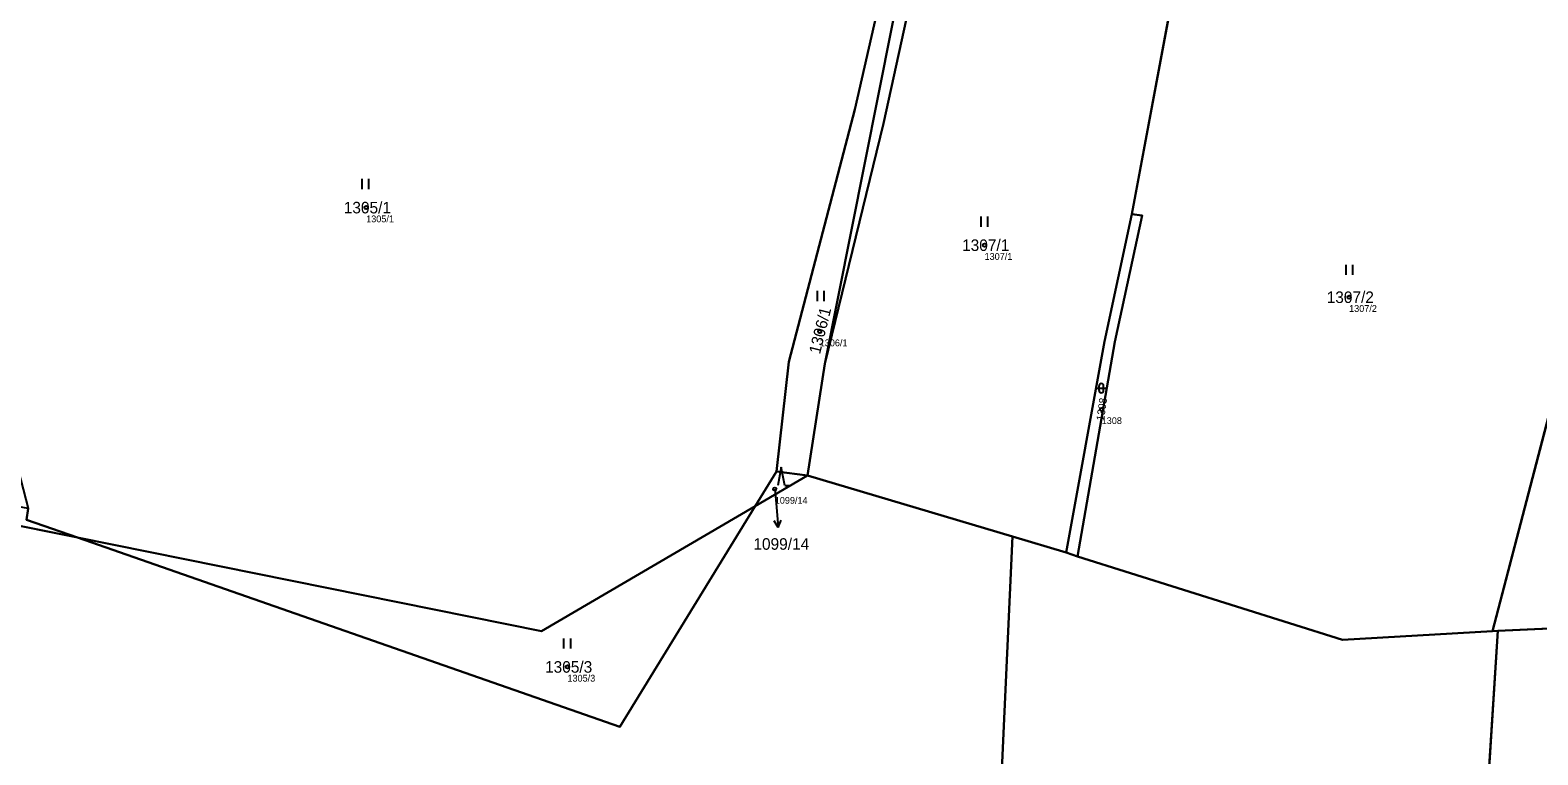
# Model space of a CAD drawing. Extents: x -754731 to -751381, y -1060564 to -1058101.
# Drawn here: x -753239.2 to -753017.1, y -1059498.8 to -1059392.2 of the extents above; entities that cross this region are included whole.
import ezdxf

# ---------------------------------------------------------------- set-up
doc = ezdxf.new("R2010")
doc.units = 0
for name, color, linetype in [('Definiční body', 7, 'Continuous'), ('Hranice parcel', 7, 'Continuous'), ('Parcelní čísla', 7, 'Continuous'), ('Polygon parcely', 7, 'Continuous'), ('Pop  PČ popisy', 7, 'Continuous'), ('Značky kultur', 7, 'Continuous')]:
    doc.layers.add(name, color=color, linetype=linetype)

msp = doc.modelspace()

# ---------------------------------------------------------------- linework, layer by layer
at = {"layer": 'Definiční body'}
for centre in [(-753189.67, -1059418.28), (-753098.61, -1059423.81), (-753044.93, -1059431.47), (-753122.88, -1059436.53), (-753081.36, -1059447.98), (-753129.5, -1059459.71), (-753160.03, -1059485.89)]:
    msp.add_circle(centre, 0.25, dxfattribs=at)
at = {"layer": 'Hranice parcel'}
for p, q in [((-753122.14, -1059441.27), (-753108.33, -1059371.96)), ((-753076.91, -1059419.23), (-753069.61, -1059380.18)), ((-753001.15, -1059393.75), (-753023.79, -1059480.61)), ((-753124.7, -1059457.73), (-753122.14, -1059441.27)), ((-753132.37, -1059462.22), (-753129.23, -1059457.1)), ((-753132.37, -1059462.22), (-753124.7, -1059457.73)), ((-753124.7, -1059457.73), (-753129.23, -1059457.1)), ((-753094.51, -1059466.71), (-753124.7, -1059457.73)), ((-753251.49, -1059462.95), (-753232.16, -1059466.85)), ((-753094.51, -1059466.71), (-753097.3, -1059527.86)), ((-753086.61, -1059469.06), (-753094.51, -1059466.71)), ((-753086.61, -1059469.06), (-753084.91, -1059469.63)), ((-753023.01, -1059480.58), (-752952.57, -1059477.41)), ((-753023.01, -1059480.58), (-753032.16, -1059623.34)), ((-753023.79, -1059480.61), (-753023.01, -1059480.58))]:
    msp.add_line(p, q, dxfattribs=at)
for points in [[(-753129.23, -1059457.1), (-753127.44, -1059440.99), (-753117.69, -1059403.86), (-753110.37, -1059371.53)], [(-753122.14, -1059441.27), (-753113.51, -1059405.91), (-753106.36, -1059373.37), (-753105.74, -1059372.51)], [(-753076.91, -1059419.23), (-753080.95, -1059437.97), (-753086.61, -1059469.06)], [(-753084.91, -1059469.63), (-753079.44, -1059438.04), (-753075.41, -1059419.43), (-753076.91, -1059419.23)], [(-753232.16, -1059466.85), (-753163.85, -1059480.64), (-753132.37, -1059462.22)], [(-753132.37, -1059462.22), (-753152.3, -1059494.72), (-753232.16, -1059466.85)], [(-753239.44, -1059462.59), (-753239.7, -1059464.22), (-753232.16, -1059466.85)], [(-753023.79, -1059480.61), (-753045.91, -1059481.9), (-753084.91, -1059469.63)]]:
    msp.add_lwpolyline(points, dxfattribs=at)
at = {"layer": 'Polygon parcely'}
for points in [[(-753239.44, -1059462.59), (-753239.7, -1059464.22), (-753232.16, -1059466.85), (-753163.85, -1059480.64), (-753132.37, -1059462.22), (-753129.23, -1059457.1), (-753127.44, -1059440.99), (-753117.69, -1059403.86), (-753110.37, -1059371.53), (-753147.19, -1059363.71), (-753183.61, -1059356.78), (-753206.83, -1059350.65), (-753219.49, -1059351.78), (-753239.61, -1059348.46), (-753248.89, -1059342.51), (-753251.38, -1059347.17), (-753248.12, -1059396.35), (-753248.71, -1059432.04), (-753249.99, -1059436.96), (-753251.9, -1059439.87), (-753245.37, -1059439.81)], [(-753122.14, -1059441.27), (-753108.33, -1059371.96), (-753110.37, -1059371.53), (-753117.69, -1059403.86), (-753127.44, -1059440.99), (-753129.23, -1059457.1), (-753124.7, -1059457.73)], [(-753069.61, -1059380.18), (-753105.74, -1059372.51), (-753106.36, -1059373.37), (-753113.51, -1059405.91), (-753122.14, -1059441.27), (-753124.7, -1059457.73), (-753094.51, -1059466.71), (-753086.61, -1059469.06), (-753080.95, -1059437.97), (-753076.91, -1059419.23)], [(-753113.51, -1059405.91), (-753106.36, -1059373.37), (-753105.74, -1059372.51), (-753108.33, -1059371.96), (-753122.14, -1059441.27)], [(-753084.91, -1059469.63), (-753045.91, -1059481.9), (-753023.79, -1059480.61), (-753001.15, -1059393.75), (-753022.88, -1059387.98), (-753046.17, -1059383.23), (-753063.28, -1059382.9), (-753069.61, -1059380.18), (-753076.91, -1059419.23), (-753075.41, -1059419.43), (-753079.44, -1059438.04)], [(-752984.23, -1059398.75), (-753001.15, -1059393.75), (-753023.79, -1059480.61), (-753023.01, -1059480.58), (-752952.57, -1059477.41), (-752940.93, -1059476.89), (-752937.74, -1059463.82), (-752937.1, -1059461.21), (-752923.95, -1059415.07), (-752923.3, -1059412.8)], [(-753079.44, -1059438.04), (-753075.41, -1059419.43), (-753076.91, -1059419.23), (-753080.95, -1059437.97), (-753086.61, -1059469.06), (-753084.91, -1059469.63)], [(-753182.66, -1059567.3), (-753100.43, -1059521.77), (-753097.3, -1059527.86), (-753094.51, -1059466.71), (-753124.7, -1059457.73), (-753132.37, -1059462.22), (-753152.3, -1059494.72), (-753232.16, -1059466.85), (-753251.49, -1059462.95), (-753247.8, -1059512.2)], [(-753124.7, -1059457.73), (-753129.23, -1059457.1), (-753132.37, -1059462.22)], [(-753232.16, -1059466.85), (-753239.7, -1059464.22), (-753239.44, -1059462.59), (-753251.69, -1059460.25), (-753251.49, -1059462.95)], [(-753232.16, -1059466.85), (-753152.3, -1059494.72), (-753132.37, -1059462.22), (-753163.85, -1059480.64)], [(-753045.91, -1059481.9), (-753084.91, -1059469.63), (-753086.61, -1059469.06), (-753094.51, -1059466.71), (-753097.3, -1059527.86), (-753089.43, -1059543.15), (-753094.66, -1059553.62), (-753092.71, -1059600.13), (-753100.71, -1059602.81), (-753102.26, -1059636.83), (-753070.37, -1059630.8), (-753032.16, -1059623.34), (-753023.01, -1059480.58), (-753023.79, -1059480.61)], [(-753008.94, -1059621.27), (-752952.13, -1059591.52), (-752952.57, -1059477.41), (-753023.01, -1059480.58), (-753032.16, -1059623.34)]]:
    msp.add_lwpolyline(points, close=True, dxfattribs=at)
at = {"layer": 'Pop  PČ popisy'}
for p, q in [((-753129.5, -1059459.71), (-753129.24, -1059462.36)), ((-753128.98, -1059465.35), (-753129.57, -1059464.4)), ((-753129.24, -1059462.36), (-753128.98, -1059465.35)), ((-753128.98, -1059465.35), (-753128.57, -1059464.31))]:
    msp.add_line(p, q, dxfattribs=at)
at = {"layer": 'Značky kultur'}
for p, q in [((-753190.26, -1059415.56), (-753190.26, -1059414.06)), ((-753189.26, -1059415.56), (-753189.26, -1059414.06)), ((-753099.12, -1059421.11), (-753099.12, -1059419.61)), ((-753098.12, -1059421.11), (-753098.12, -1059419.61)), ((-753045.37, -1059428.18), (-753045.37, -1059426.68)), ((-753044.37, -1059428.18), (-753044.37, -1059426.68)), ((-753123.21, -1059432.03), (-753123.21, -1059430.53)), ((-753122.21, -1059432.03), (-753122.21, -1059430.53)), ((-753082.09, -1059444.85), (-753080.75, -1059444.85)), ((-753081.76, -1059444.52), (-753081.76, -1059445.19)), ((-753081.08, -1059445.19), (-753081.08, -1059444.52)), ((-753128.54, -1059456.49), (-753129.04, -1059459.17)), ((-753128.04, -1059459.17), (-753128.54, -1059456.49)), ((-753128.04, -1059459.17), (-753127.37, -1059459.17)), ((-753160.54, -1059483.19), (-753160.54, -1059481.69)), ((-753159.54, -1059483.19), (-753159.54, -1059481.69))]:
    msp.add_line(p, q, dxfattribs=at)
for centre, start, end in [((-753081.42, -1059444.52), 0, 180), ((-753081.42, -1059445.19), 180, 359.9879)]:
    msp.add_arc(centre, 0.335, start, end, dxfattribs=at)

# ---------------------------------------------------------------- texts
at = {"layer": 'Definiční body'}
for s, p in [('1305/1', (-753189.67, -1059420.44)), ('1307/1', (-753098.61, -1059425.97)), ('1307/2', (-753044.93, -1059433.63)), ('1306/1', (-753122.88, -1059438.69)), ('1308', (-753081.36, -1059450.14)), ('1099/14', (-753129.5, -1059461.87)), ('1305/3', (-753160.03, -1059488.05))]:
    msp.add_text(s, height=1, dxfattribs=at).set_placement(p)
at = {"layer": 'Parcelní čísla'}
for s, p in [('1305/1', (-753192.97, -1059419.13)), ('1307/1', (-753101.92, -1059424.66)), ('1307/2', (-753048.23, -1059432.32)), ('1099/14', (-753132.65, -1059468.64)), ('1305/3', (-753163.33, -1059486.74))]:
    msp.add_text(s, height=1.7, dxfattribs=at).set_placement(p)
for s, height, rotation, p in [('1306/1', 1.7, 76, (-753122.85, -1059439.94)), ('1308', 1.139, 82, (-753081.03, -1059449.72))]:
    msp.add_text(s, height=height, rotation=rotation, dxfattribs=at).set_placement(p)

doc.saveas('drawing.dxf')
